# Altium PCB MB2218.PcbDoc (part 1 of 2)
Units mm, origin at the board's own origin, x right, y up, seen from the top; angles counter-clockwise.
Board outline 43 x 47 mm, 4 copper layers (Top Layer, Signal Layer 1, Signal Layer 2, Bottom Layer), stack 1.539 mm thick; 90 components, 71 nets, 361 pads, 605 vias.
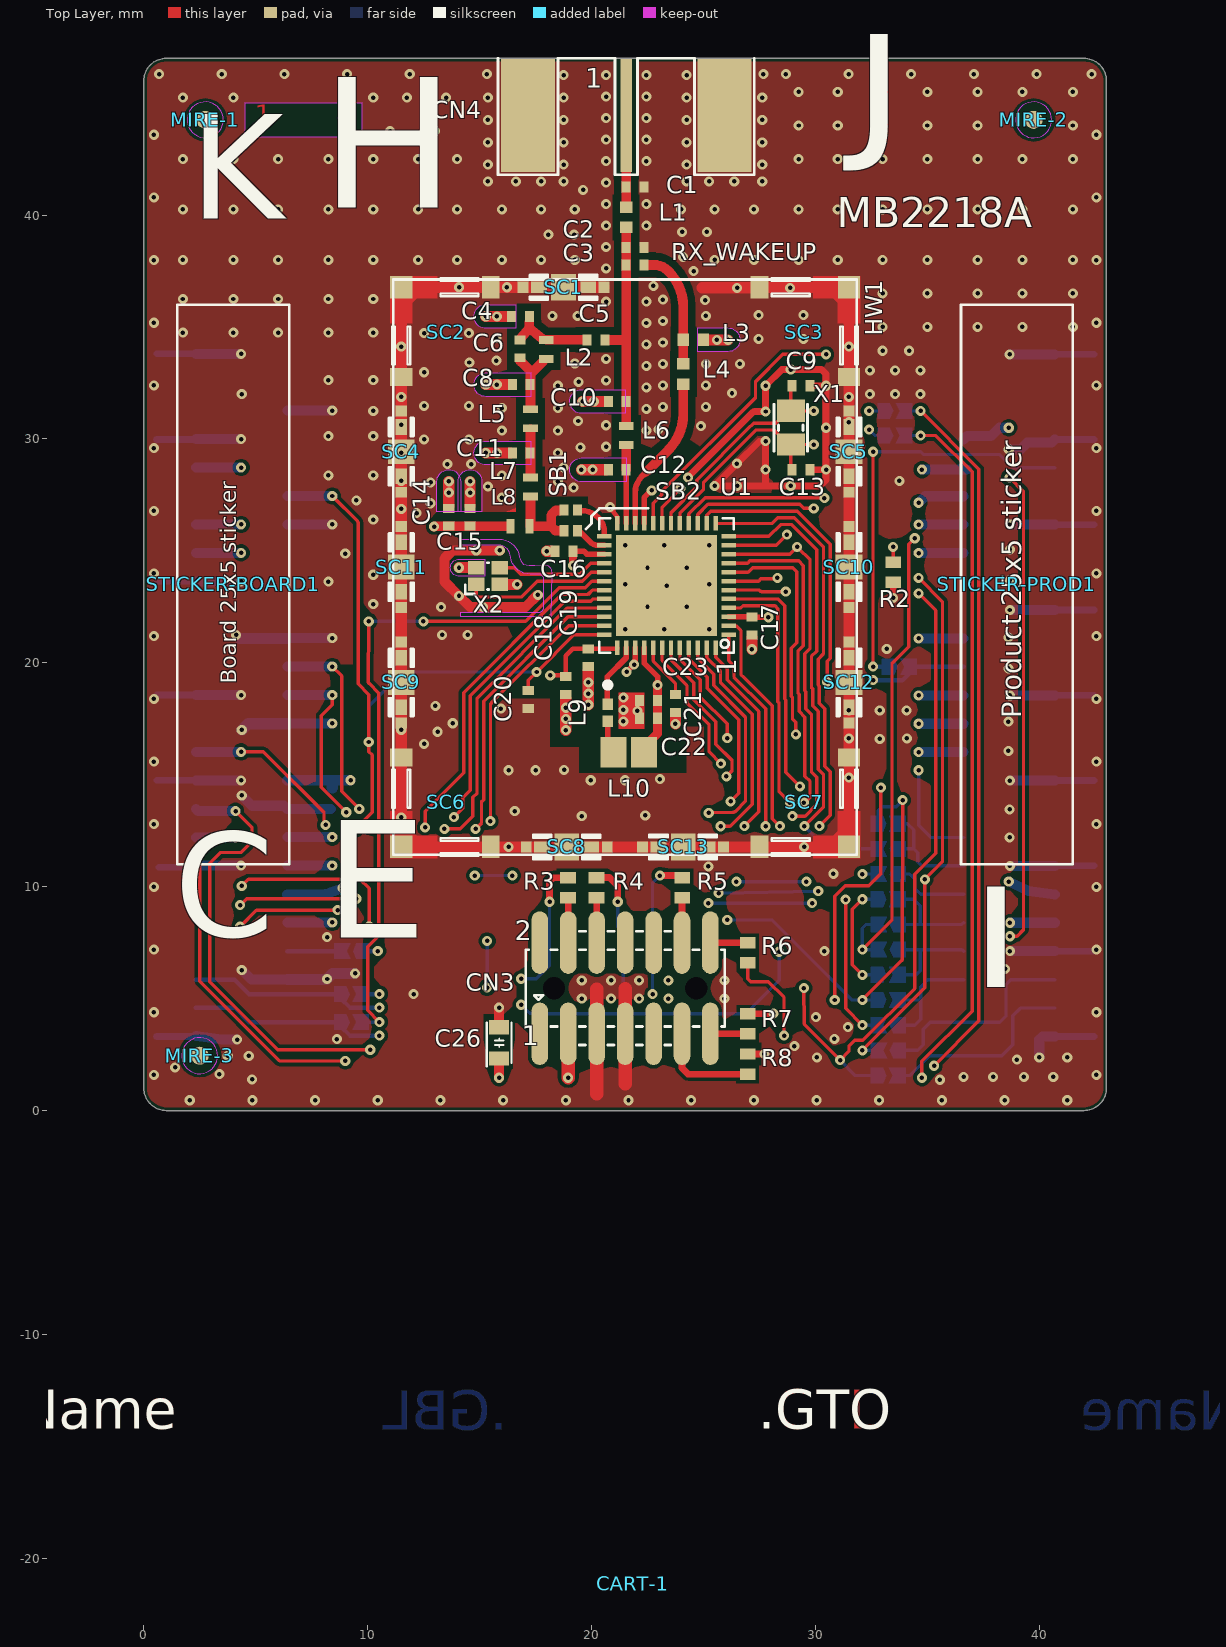
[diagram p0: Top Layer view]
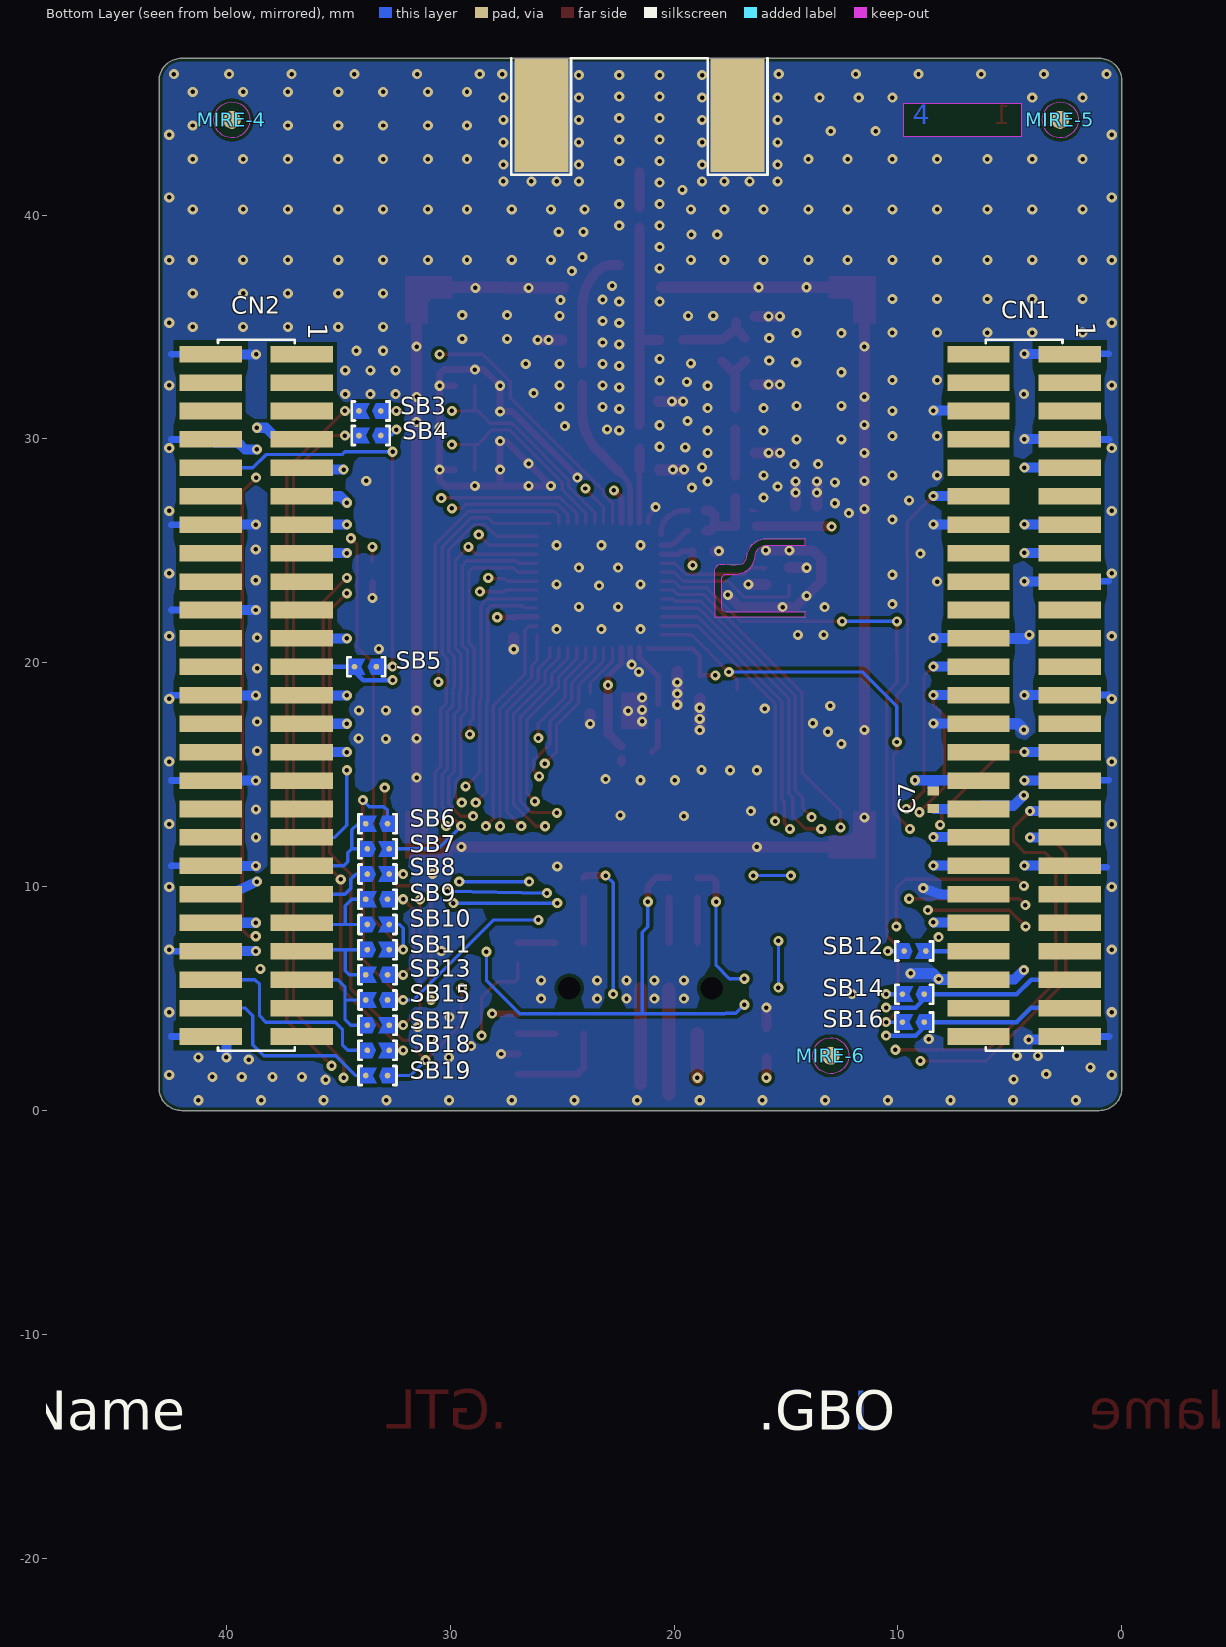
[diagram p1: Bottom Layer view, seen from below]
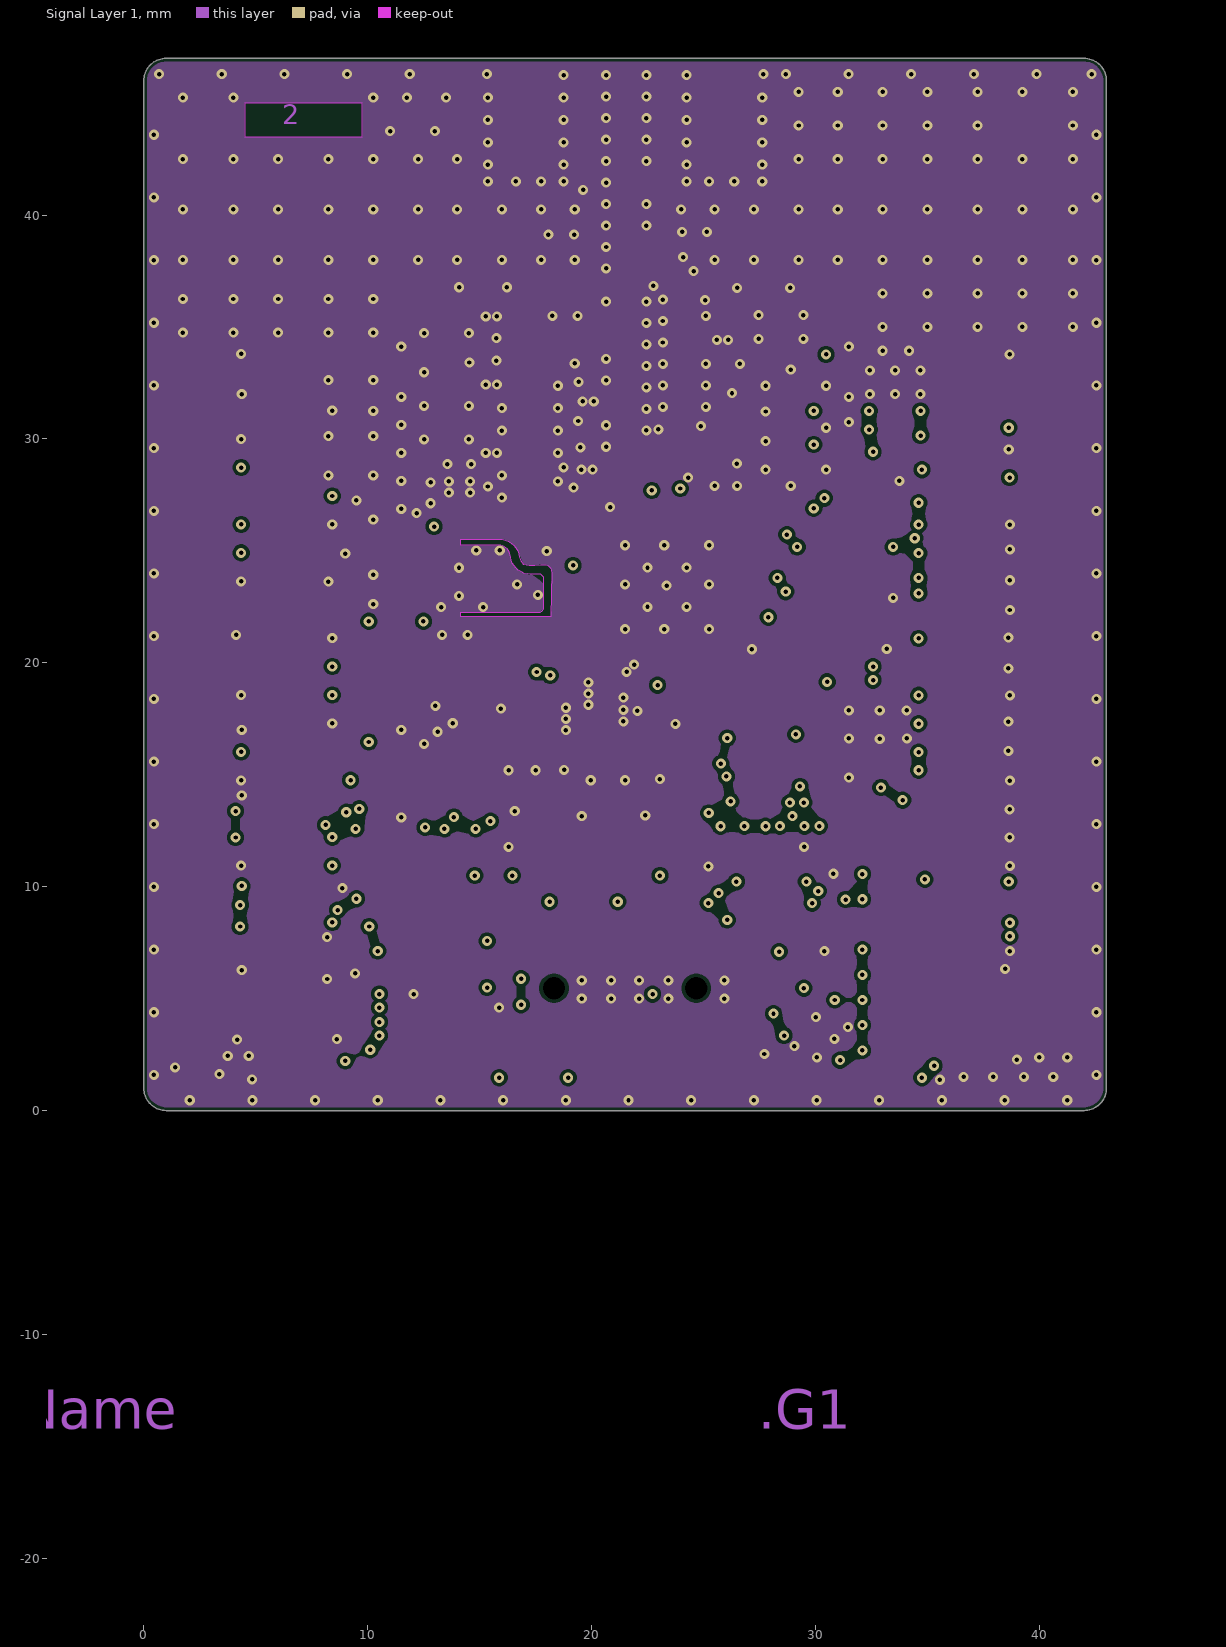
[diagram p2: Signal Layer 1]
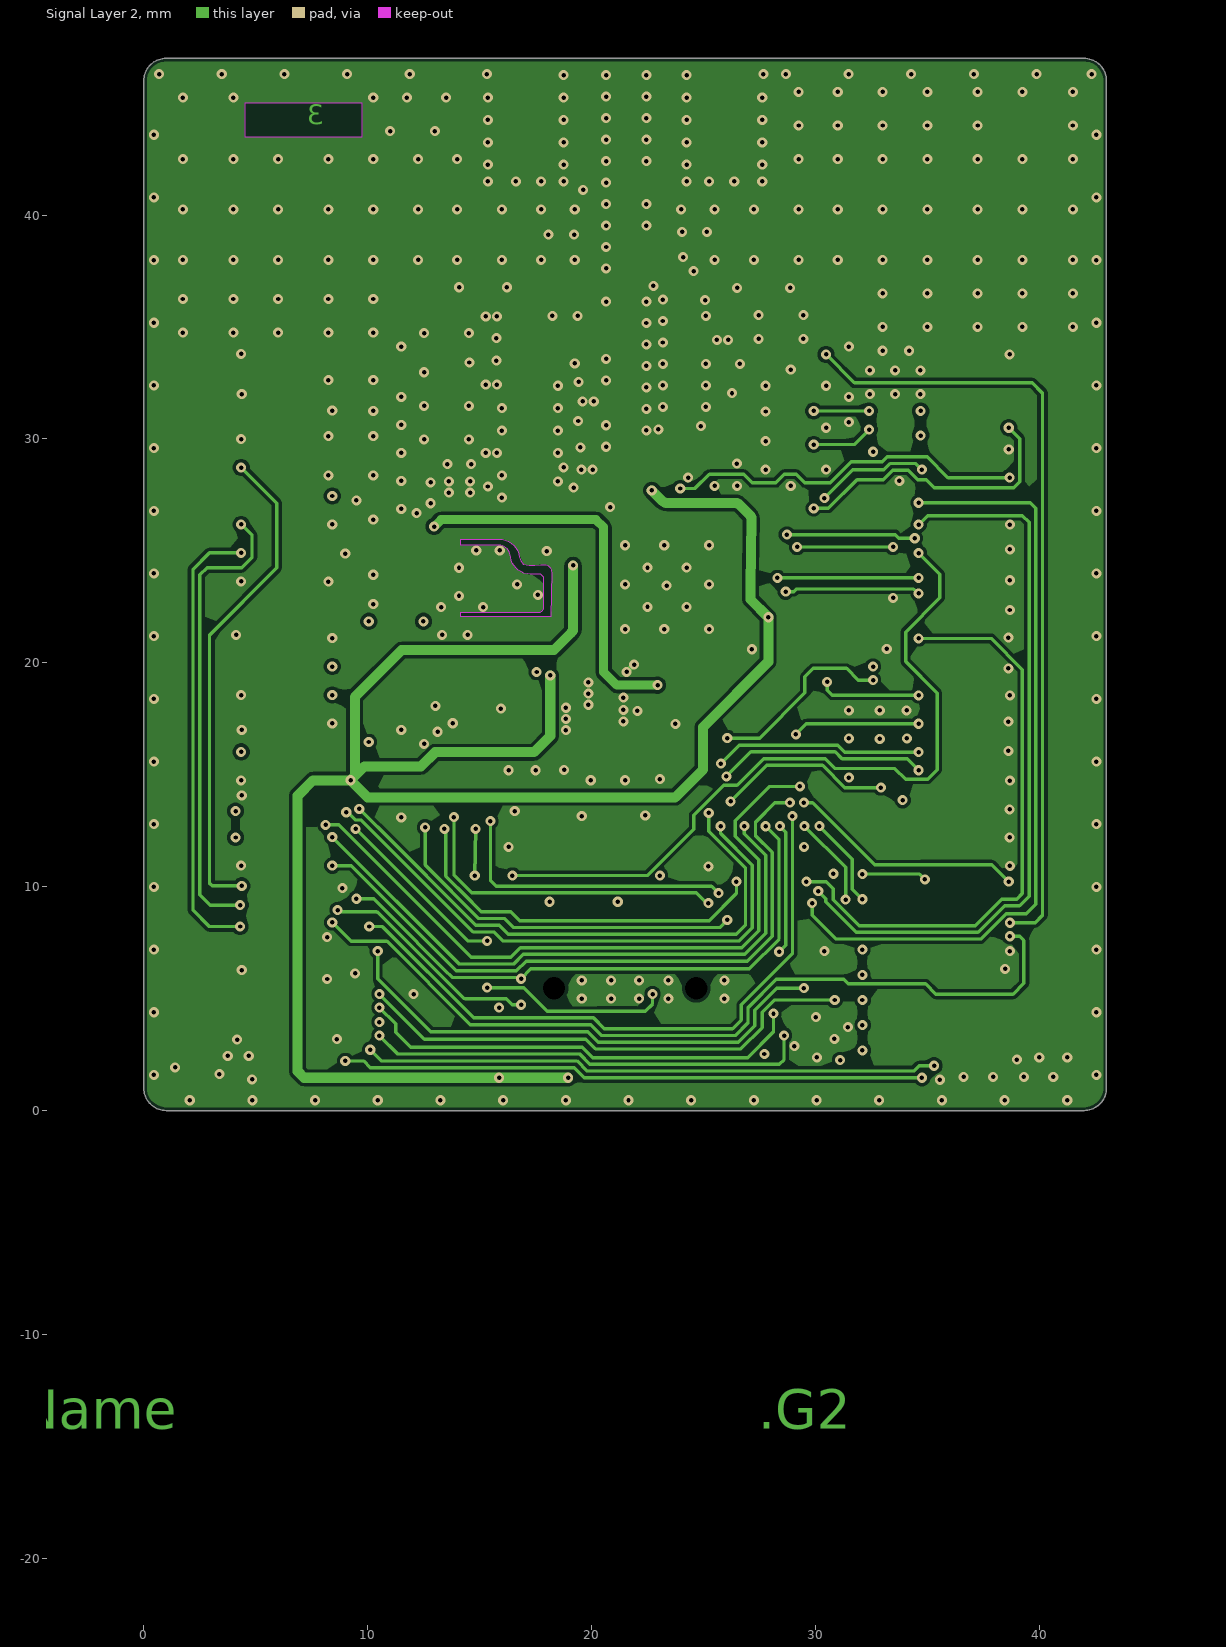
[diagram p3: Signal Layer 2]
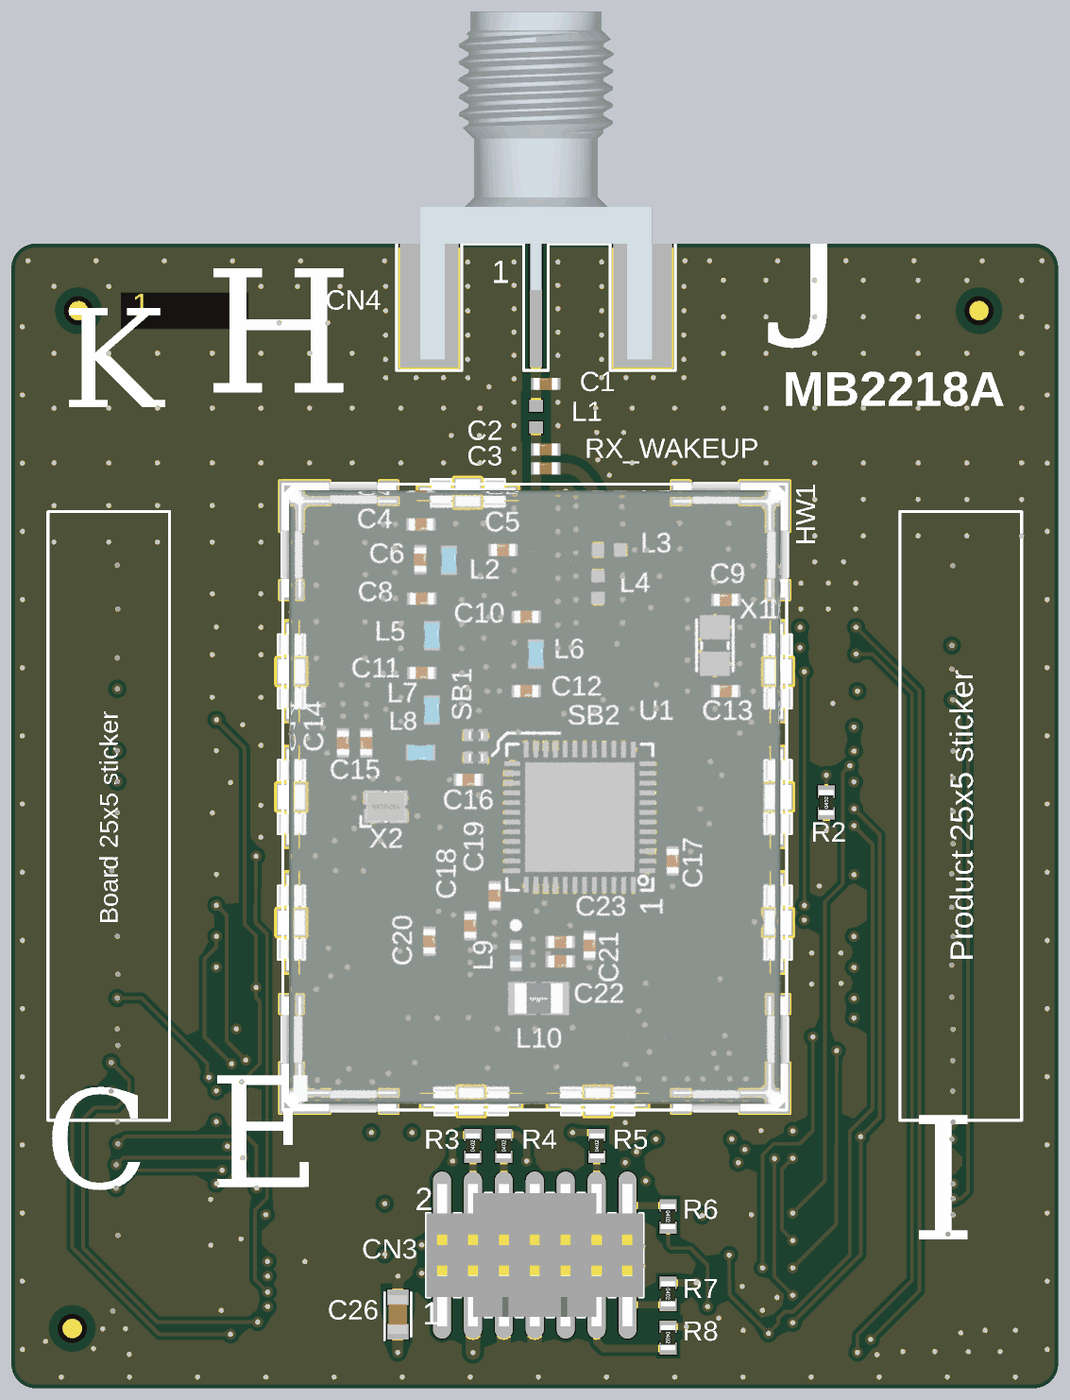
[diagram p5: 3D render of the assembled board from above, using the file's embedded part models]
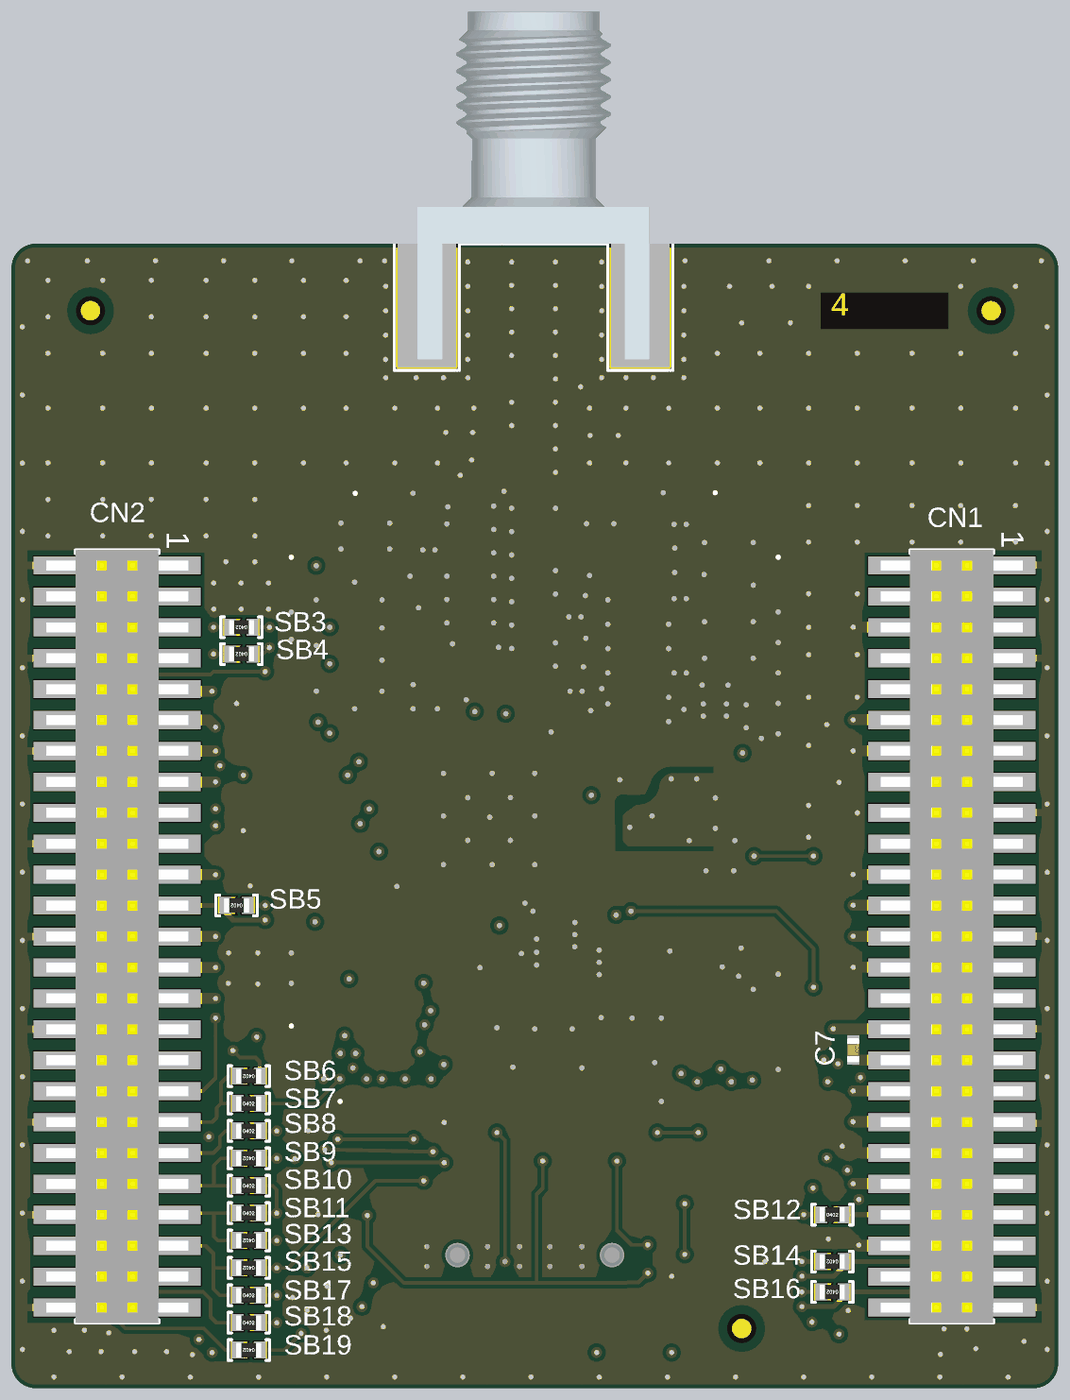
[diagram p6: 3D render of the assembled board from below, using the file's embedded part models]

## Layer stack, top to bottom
Top Solder: solder mask 0.0102, Solder Resist, Dk 3.5
Top Layer: signal copper 0.0406
Dielectric 1: core 0.254, FR4 VT-47, Dk 4
Signal Layer 1: signal copper 0.0178
Dielectric 2: core 0.9144, FR4 VT-47, Dk 4.3
Signal Layer 2: signal copper 0.0178
Dielectric 3: core 0.254, FR4 VT-47, Dk 4
Bottom Layer: signal copper 0.0406
Bottom Solder: solder mask 0.0102, Solder Resist, Dk 3.5

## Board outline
0,1 ccw(c1,1) 1,0 42,0 ccw(c42,1) 43,1 43,46 ccw(c42,46) 42,47 1,47 ccw(c1,46) 0,46

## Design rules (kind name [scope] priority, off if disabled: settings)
BoardOutlineClearance [All] p1: gap=0.14 ignorepadtopadclearanceinfootprint=FALSE
Clearance Clearance_Keepout [All vs IsKeepOut] p1: gap=0.15 ignorepadtopadclearanceinfootprint=TRUE except(0: Poly-Region)
Clearance Clearance_RF-50R [InNetClass('NC_RF-50R')] p2: gap=0.335 ignorepadtopadclearanceinfootprint=FALSE except(0.15: Arc-Arc Arc-Track Arc-SMDPad Arc-Via Track-Track Track-SMDPad Track-Via SMDPad-Via Via-Via Via-Fill Via-Region Via-Text Via-Hole; 0.2: SMDPad-SMDPad)
Clearance Clearance_Default_Same-net_GND [InNet('GND')] p3: gap=0.15 ignorepadtopadclearanceinfootprint=TRUE except(0: Arc-SMDPad Arc-Via Track-SMDPad Track-Via Track-Hole SMDPad-Via SMDPad-Hole THPad-Via Via-Via Via-Region Via-Hole; 0.12: SMDPad-SMDPad)
Clearance Clearance_Default_Same-net [All] p4: gap=0.15 ignorepadtopadclearanceinfootprint=TRUE except(0.1: Via-Via; 0.12: Arc-SMDPad Track-SMDPad SMDPad-SMDPad)
Clearance Clearance_Default [All] p5: gap=0.15 ignorepadtopadclearanceinfootprint=FALSE except(0.1: Arc-Via Track-Via)
ComponentClearance [All] p1: gap=0.165 collisioncheckmode=3 verticalgap=0.165 showdistances=FALSE
HoleSize [All] p1: absolutevalues=TRUE maxlimit=10 minlimit=0.025 maxpercent=80.000 minpercent=20.000
HoleToHoleClearance [All] p1: gap=0.2 allowstackedmicrovias=TRUE
MinimumSolderMaskSliver [All] p1: minsoldermaskwidth=0.1
PlaneConnect [All] p1: planeconnectstyle=Relief reliefexpansion=0.508 reliefentries=4 reliefconductorwidth=0.21 reliefairgap=0.21
PolygonConnect PolygonConnect_clip [TouchesRoom('RoomDefinition')or TouchesRoom('RoomDefinition_2') or   TouchesRoom('RoomDefinition_1') OR TouchesRoom('RoomDefinition_3') or  TouchesRoom('RoomDefinition_4')  or TouchesRoom('RoomDefinition_5')] p1: connectstyle=Direct reliefconductorwidth=0.254 reliefentries=4 polygonreliefangle="90 Angle" airgapwidth=0.254
PolygonConnect PolygonConnect_Default [All] p2: thpad.connectstyle=Relief thpad.reliefconductorwidth=0.3 thpad.reliefentries=4 thpad.polygonreliefangle="90 Angle" thpad.airgapwidth=0.25 smdpad.connectstyle=NoConnect smdpad.reliefconductorwidth=0.254 smdpad.reliefentries=4 smdpad.polygonreliefangle="90 Angle" smdpad.airgapwidth=0.254 via.connectstyle=Direct via.reliefconductorwidth=0.254 via.reliefentries=4 via.polygonreliefangle="90 Angle" via.airgapwidth=0.254
RoomDefinition RoomDefinition_5 [False vs False] p1: confinementstyle=ConfineIn formatcopy=TRUE lockcomponents=FALSE outline 20.2,27.657 21.45,27.657 21.45,25.9 20.2,25.9
RoomDefinition RoomDefinition_4 [False vs False] p2: confinementstyle=ConfineIn formatcopy=TRUE lockcomponents=FALSE outline 16.668,18.313 18.139,18.313 18.139,17.066 16.668,17.066
RoomDefinition RoomDefinition_3 [False vs False] p3: confinementstyle=ConfineIn formatcopy=TRUE lockcomponents=FALSE outline 22.14,41.754 23.059,41.754 23.059,38.308 22.14,38.308
RoomDefinition RoomDefinition_1 [False vs False] p4: confinementstyle=ConfineIn formatcopy=TRUE lockcomponents=FALSE outline 30.617,26.64 32.517,26.64 32.517,16.661 30.617,16.661
RoomDefinition [False vs False] p5: confinementstyle=ConfineIn formatcopy=TRUE lockcomponents=FALSE outline 10.617,26.639 12.517,26.639 12.517,16.661 10.617,16.661
RoomDefinition RoomDefinition_2 [False] p6: confinementstyle=ConfineIn formatcopy=TRUE lockcomponents=FALSE outline 15.917,11.028 15.917,12.613 26.825,12.613 26.825,11.028
RoutingVias RoutingVias_Default [All] p1: holewidth=0.3 width=0.6 viastyle="Through Hole" minholewidth=0.3 minwidth=0.6 maxholewidth=0.3 maxwidth=0.6 useviatemplates=TRUE viatemplateguid#1={99C878AE-A8D1-4413-99BF-86AA8753CADB} viatemplatename#1=v45h20m0mx0
SilkToSilkClearance [All] p1 off: silktosilkclearance=0.2
SilkToSolderMaskClearance [IsPad] p1 off: minsilkscreentomaskgap=0.2 clearancetoexposedcopper=TRUE
SolderMaskExpansion [All] p1: expansion=0.102 istentingtop=FALSE
ViasUnderSMD [InPadClass('PC__VIAS-IN-PAD')] p1: allowed=TRUE
Width Width_RF-50R [InNetClass('NC_RF-50R')] p1: maxlimit=0.45 minlimit=0.25 preferedwidth=0.254 toplayer_prefwidth=0.44 impedanceprofiledriven=TRUE impedanceprofileid={AD1550EC-3D0E-4E34-9E21-FD44D1EEEC04} impedanceprofilevalue=50.000000 minimp=50.000000 maximp=50.000000 favimp=50.000000
Width Width_Default [All] p2: maxlimit=10 minlimit=0.15 preferedwidth=0.2
23 further rules are at their usual default settings.

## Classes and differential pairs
pad class PC__VIAS-IN-PAD: C22-1 C22-2 C23-1 C23-2 U1-49
net class NC_RF-50R: NetC1_2 NetC2_2 NetC3_1 NetC4_2 NetC6_1 NetC11_2 NetC12_2 NetL4_1 NetL7_1

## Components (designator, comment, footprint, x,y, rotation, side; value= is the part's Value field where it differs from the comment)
C1 "Capacitor" GRM155--GJM155-0_05-MFG 21.95,41.25 r180 top value=TBD
C2 "Capacitor" GRM155--GJM155-0_05-MFG 21.95,38.55 r180 top value=TBD
C3 "Capacitor" GRM155--GJM155-0_05-MFG 21.95,37.775 r180 top value=TBD
C4 "Capacitor" GRM155--GJM155-0_05-MFG 16.825,35.475 r0 top value=TBD
C5 "Capacitor" GRM155--GJM155-0_05-MFG 20.2,34.425 r180 top value=TBD
C6 "Capacitor" GRM155--GJM155-0_05-MFG 16.8,34.025 r90 top value=TBD
C7 "Capacitor" GRM155--GJM155-0_05-MFG 8.42,13.882 r90 bottom value=TBD
C8 "Capacitor" GRM155--GJM155-0_05-MFG 16.86,32.425 r0 top value=TBD
C9 "Capacitor" GRM155--GJM155-0_05-MFG 29.35,32.375 r180 top value=6.8pF
C10 "Capacitor" GRM155--GJM155-0_05-MFG 21.15,31.675 r0 top value=TBD
C11 "Capacitor" GRM155--GJM155-0_05-MFG 16.86,29.375 r0 top value=TBD
C12 "Capacitor" GRM155--GJM155-0_05-MFG 21.15,28.625 r0 top value=TBD
C13 "Capacitor" GRM155--GJM155-0_05-MFG 29.35,28.625 r180 top value=6.8pF
C14 "Capacitor" GRM155--GJM155-0_05-MFG 13.625,26.5 r90 top value=100pF
C15 "Capacitor" GRM155--GJM155-0_05-MFG 14.575,26.5 r270 top value=100nF
C16 "Capacitor" GRM155--GJM155-0_05-MFG 18.775,24.985 r0 top value=100nF
C17 "Capacitor" GRM155--GJM155-0_05-MFG 27.163,21.65 r90 top value=100nF
C18 "Capacitor" GRM155--GJM155-0_05-MFG 18.852,18.99 r90 top value=4.7uF
C19 "Capacitor" GRM155--GJM155-0_05-MFG 19.857,20.225 r90 top value=TBD
C20 "Capacitor" GRM155--GJM155-0_05-MFG 17.172,18.352 r90 top value=100nF
C21 "Capacitor" GRM155--GJM155-0_05-MFG 23.75,18.175 r90 top value=220nF
C22 "Capacitor" GRM155--GJM155-0_05-MFG 22.55,17.525 r0 top value=4.7uF
C23 "Capacitor" GRM155--GJM155-0_05-MFG 22.55,18.321 r180 top value=100nF
C26 "Capacitor" C0603 15.875,3.025 r270 top value=1uF
CART-1 "Comment" Sheetbox_4L2S -23.25,-26.5 r0 top
CN1 "FTSH-125-02-L-DV" CON_SAMTEC_FTSH-125-02-L-DV_INV 4.366,18.548 r270 bottom locked value="Header 25x2"
CN2 "FTSH-125-02-L-DV" CON_SAMTEC_FTSH-125-02-L-DV_INV 38.656,18.548 r270 bottom locked value="Header 25x2"
CN3 "Header 7x2" CON_SAMTEC_FTSH-107-01-L-DV-K-A 21.5,5.465 r0 top locked
CN4 "mmcx" CON_SMA-RF_CINCH_142-0701-851 21.55,47 r0 top
HW1 "S02-20150300" SHIELD_HARWIN_S02-25200300_20X25_H3 21.5,24.275 r0 top locked value=S02-25200300R
L1 "Inductor" L0402 21.55,39.9 r90 top value=0R
L2 "Inductor" LQW15AN_00-W0_6-0_1-MFG 17.975,34 r90 top value=TBD
L3 "Inductor" L0402 24.55,34.425 r0 top value=TBD
L4 "Inductor" L0402 24.1,32.9 r90 top value=TBD
L5 "Inductor" LQW15AN_00-W0_6-0_1-MFG 17.275,30.9 r90 top value=TBD
L6 "Inductor" LQW15AN_00-W0_6-0_1-MFG 21.55,30.15 r90 top value=TBD
L7 "Inductor" LQW15AN_00-W0_6-0_1-MFG 17.275,27.85 r90 top value=TBD
L8 "Inductor" LQW15AN_00-W0_6-0_1-MFG 16.81,26.1 r0 top value=TBD
L9 "Inductor" LQG15HH_02-IPC_C 20.725,17.773 r270 top value=100nH
L10 "Inductor" LQM21FN_70-IPC_C 21.663,16.008 r180 top value=10µH
MIRE-1 "Comment" MIRE_PLACE_SMD_0P8MM 2.75,44.25 r0 top
MIRE-2 "Comment" MIRE_PLACE_SMD_0P8MM 39.75,44.25 r0 top
MIRE-3 "Comment" MIRE_PLACE_SMD_0P8MM 2.5,2.45 r0 top
MIRE-4 "Comment" MIRE_PLACE_SMD_0P8MM 39.75,44.25 r180 bottom
MIRE-5 "Comment" MIRE_PLACE_SMD_0P8MM 2.75,44.25 r180 bottom
MIRE-6 "Comment" MIRE_PLACE_SMD_0P8MM 13,2.45 r180 bottom
R2 "Resistor" R0402 33.475,24.05 r90 top value=100K
R3 "Resistor" R0402 18.95,9.95 r90 top value=47R
R4 "Resistor" R0402 20.225,9.95 r90 top value=47R
R5 "Resistor" R0402 24.05,9.95 r90 top value=47R
R6 "Resistor" R0402 26.975,7.05 r270 top value=47R
R7 "Resistor" R0402 26.975,3.875 r270 top value=47R
R8 "Resistor" R0402 26.975,2.075 r270 top value=47R
SB1 "SB_ON" SOLDER-BRIDGE_R0201_0R 19.075,26.821 r180 top value=0R
SB2 "SB_ON" SOLDER-BRIDGE_R0201_0R 19.075,25.9 r180 top value=0R
SB3 "SB_ON" SOLDER-BRIDGE_R0402-0R 33.55,31.25 r0 bottom
SB4 "SB_ON" SOLDER-BRIDGE_R0402-0R 33.55,30.15 r0 bottom
SB5 "SB_ON" SOLDER-BRIDGE_R0402-0R 33.75,19.825 r0 bottom
SB6 "SB_ON" SOLDER-BRIDGE_R0402-0R 33.25,12.812 r0 bottom
SB7 "SB_ON" SOLDER-BRIDGE_R0402-0R 33.25,11.688 r180 bottom
SB8 "SB_ON" SOLDER-BRIDGE_R0402-0R 33.25,10.563 r180 bottom
SB9 "SB_ON" SOLDER-BRIDGE_R0402-0R 33.25,9.437 r0 bottom
SB10 "SB_ON" SOLDER-BRIDGE_R0402-0R 33.25,8.313 r180 bottom
SB11 "SB_ON" SOLDER-BRIDGE_R0402-0R 33.25,7.187 r180 bottom
SB12 "SB_ON" SOLDER-BRIDGE_R0402-0R 9.275,7.125 r180 bottom
SB13 "SB_ON" SOLDER-BRIDGE_R0402-0R 33.25,6.062 r0 bottom
SB14 "SB_ON" SOLDER-BRIDGE_R0402-0R 9.275,5.2 r0 bottom
SB15 "SB_ON" SOLDER-BRIDGE_R0402-0R 33.25,4.938 r0 bottom
SB16 "SB_ON" SOLDER-BRIDGE_R0402-0R 9.275,3.95 r0 bottom
SB17 "SB_ON" SOLDER-BRIDGE_R0402-0R 33.25,3.812 r180 bottom
SB18 "SB_ON" SOLDER-BRIDGE_R0402-0R 33.25,2.688 r180 bottom
SB19 "SB_ON" SOLDER-BRIDGE_R0402-0R 33.25,1.562 r0 bottom
SC1 "Shield-clip_S0951-46R" CLIP_HARWIN_S0951-46R 18.75,36.775 r180 top value=S0951-46R
SC2 "Shield-clip_S0951-46R" CLIP_HARWIN_S0981-46R 11.5,36.775 r180 top value=S0981-46R
SC3 "Shield-clip_S0951-46R" CLIP_HARWIN_S0981-46R 31.5,36.775 r90 top value=S0981-46R
SC4 "Shield-clip_S0951-46R" CLIP_HARWIN_S0951-46R 11.5,29.433 r90 top value=S0951-46R
SC5 "Shield-clip_S0951-46R" CLIP_HARWIN_S0951-46R 31.5,29.433 r90 top value=S0951-46R
SC6 "Shield-clip_S0951-46R" CLIP_HARWIN_S0981-46R 11.5,11.775 r270 top value=S0981-46R
SC7 "Shield-clip_S0951-46R" CLIP_HARWIN_S0981-46R 31.5,11.775 r0 top value=S0981-46R
SC8 "Shield-clip_S0951-46R" CLIP_HARWIN_S0951-46R 18.89,11.775 r180 top value=S0951-46R
SC9 "Shield-clip_S0951-46R" CLIP_HARWIN_S0951-46R 11.5,19.12 r270 top value=S0951-46R
SC10 "Shield-clip_S0951-46R" CLIP_HARWIN_S0951-46R 31.5,24.278 r90 top value=S0951-46R
SC11 "Shield-clip_S0951-46R" CLIP_HARWIN_S0951-46R 11.5,24.278 r270 top value=S0951-46R
SC12 "Shield-clip_S0951-46R" CLIP_HARWIN_S0951-46R 31.5,19.12 r90 top value=S0951-46R
SC13 "Shield-clip_S0951-46R" CLIP_HARWIN_S0951-46R 24.09,11.775 r180 top value=S0951-46R
STICKER-BOARD1 "Comment" STICKER_BOARD_25X5 4,23.5 r90 top
STICKER-PROD1 "Comment" STICKER_PRODUCT_25X5 39,23.5 r90 top
U1 "STM32WL33" ICC_QFN48-EPAD-4P5X4P5_6X6_P040 23.35,23.45 r180 top
X1 "XTAL_2_PINS" CRY_NX2012SA_2P 28.9,30.5 r90 top value=32.768kHz
X2 "XTAL_4_PINS" CRY_NX1612SA_4P 15.38,23.875 r0 top locked value=48MHz

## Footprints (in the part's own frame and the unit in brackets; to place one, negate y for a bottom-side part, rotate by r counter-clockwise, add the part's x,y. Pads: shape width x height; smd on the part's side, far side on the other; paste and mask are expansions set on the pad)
C0603 [mm]
  rect 0.64x0.89 smd mask+0.05: 1(-0.7,0) 2(0.7,0)
  silkscreen extent -0.9,-0.55 1.05,0.55, body extent -0.9,-0.5 0.9,0.5, height 1.4
CLIP_HARWIN_S0951-46R [mm] "MCD-01587_CLIP-X1"
  rect 0.48x0.5 smd mask+0.1: 1(-1.81,0) 1(1.81,0)
  rect 0.7x0.5 smd mask+0.1: 1(-1.1,0) 1(1.1,0)
  rect 1.1x1.2 smd mask+0.1: 1(0,0)
  silkscreen extent -1.5,-0.55 1.5,0.55, body extent -2.05,-0.65 2.05,0.65, height 1.28
CLIP_HARWIN_S0981-46R [mm] "MCD-02164"
  rect 0.8x1 smd mask+0.05: 1(-4,0)
  rect 1x0.8 smd mask+0.05: 1(0,4)
  rect 1x1 smd mask+0.05: 1(0,0)
  Top Layer region: -1.6,-0.5 0.5,-0.5 0.5,1.6 -0.5,1.6 -0.5,0.7 -0.7,0.5 -1.6,0.5
  silkscreen extent -3.45,-0.4 0.4,3.45, body extent -4.3,-0.46 0.46,4.3, height 1.4
CON_SAMTEC_FTSH-107-01-L-DV-K-A [mm] "MCD-01959"
  oval 0.74x2.79 smd mask+0.05: 1(-3.81,-2.035) 2(-3.81,2.035) 3(-2.54,-2.035) 4(-2.54,2.035) 5(-1.27,-2.035) 6(-1.27,2.035) 7(0,-2.035) 8(0,2.035) 9(1.27,-2.035) 10(1.27,2.035) 11(2.54,-2.035) 12(2.54,2.035) 13(3.81,-2.035) 14(3.81,2.035)
  round 0 hole 1 unplated paste-2539.97 mask+0.05: NPTH1(-3.175,0) NPTH2(3.175,0)
  silkscreen extent -4.44,-2.54 4.44,2.54, body extent -4.44,-2.92 4.45,2.92, height 6.12
CON_SAMTEC_FTSH-125-02-L-DV_INV [mm]
  rect 0.74x2.79 smd mask+0.05: 1(-15.24,2.035) 2(-15.24,-2.035) 3(-13.97,2.035) 4(-13.97,-2.035) 5(-12.7,2.035) 6(-12.7,-2.035) 7(-11.43,2.035) 8(-11.43,-2.035) 9(-10.16,2.035) 10(-10.16,-2.035) 11(-8.89,2.035) 12(-8.89,-2.035) 13(-7.62,2.035) 14(-7.62,-2.035) 15(-6.35,2.035) 16(-6.35,-2.035) 17(-5.08,2.035) 18(-5.08,-2.035) 19(-3.81,2.035) 20(-3.81,-2.035) 21(-2.54,2.035) 22(-2.54,-2.035) 23(-1.27,2.035) 24(-1.27,-2.035) 25(0,2.035) 26(0,-2.035) 27(1.27,2.035) 28(1.27,-2.035) 29(2.54,2.035) 30(2.54,-2.035) 31(3.81,2.035) 32(3.81,-2.035) 33(5.08,2.035) 34(5.08,-2.035) 35(6.35,2.035) 36(6.35,-2.035) 37(7.62,2.035) 38(7.62,-2.035) 39(8.89,2.035) 40(8.89,-2.035) 41(10.16,2.035) 42(10.16,-2.035) 43(11.43,2.035) 44(11.43,-2.035) 45(12.7,2.035) 46(12.7,-2.035) 47(13.97,2.035) 48(13.97,-2.035) 49(15.24,2.035) 50(15.24,-2.035)
  silkscreen extent -15.88,-1.71 15.88,1.71, body extent -15.87,-2.92 15.88,2.92, height 4.82
CON_SMA-RF_CINCH_142-0701-851 [mil] "MCD-02072"
  rect 20.08x200 smd mask+1.97: 1(0,-100)
  rect 95x200 smd mask+1.97: 2(172.48,-100) 3(-172.48,-100)
  rect 95x200 smd far side mask+1.97: 4(-172.48,-100) 5(172.48,-100)
  silkscreen extent -225,-205 225,0, body extent -189,-187 189,376, height 161
CRY_NX1612SA_4P [mm] "MCD-02262"
  rect 0.75x0.6 smd mask+0.038: 1(-0.525,-0.375) 2(0.525,-0.375) 3(0.525,0.375) 4(-0.525,0.375)
  silkscreen extent -1.02,-0.8 0.03,0.6, body extent -0.8,-0.6 0.8,0.6, height 0.31
CRY_NX2012SA_2P [mm]
  rect 1x1.25 smd mask+0.05: 1(-0.75,0) 2(0.75,0)
  silkscreen extent -1.05,-0.75 1.05,0.75, body extent -1.05,-0.63 1.05,0.63, height 0.6
GRM155--GJM155-0_05-MFG [mm]
  rect 0.4x0.5 smd paste+0 mask+0: 1(-0.4,0) 2(0.4,0)
  body extent -0.7,-0.38 0.7,0.38, height 0.25
ICC_QFN48-EPAD-4P5X4P5_6X6_P040 [mm] "MCD-03488"
  rect 0.65x0.2 smd mask+0.05: 1(-2.775,2.2) 2(-2.775,1.8) 3(-2.775,1.4) 4(-2.775,1) 5(-2.775,0.6) 6(-2.775,0.2) 7(-2.775,-0.2) 8(-2.775,-0.6) 9(-2.775,-1) 10(-2.775,-1.4) 11(-2.775,-1.8) 12(-2.775,-2.2) 25(2.775,-2.2) 26(2.775,-1.8) 27(2.775,-1.4) 28(2.775,-1) 29(2.775,-0.6) 30(2.775,-0.2) 31(2.775,0.2) 32(2.775,0.6) 33(2.775,1) 34(2.775,1.4) 35(2.775,1.8) 36(2.775,2.2)
  rect 0.2x0.65 smd mask+0.05: 13(-2.2,-2.775) 14(-1.8,-2.775) 15(-1.4,-2.775) 16(-1,-2.775) 17(-0.6,-2.775) 18(-0.2,-2.775) 19(0.2,-2.775) 20(0.6,-2.775) 21(1,-2.775) 22(1.4,-2.775) 23(1.8,-2.775) 24(2.2,-2.775) 37(2.2,2.775) 38(1.8,2.775) 39(1.4,2.775) 40(1,2.775) 41(0.6,2.775) 42(0.2,2.775) 43(-0.2,2.775) 44(-0.6,2.775) 45(-1,2.775) 46(-1.4,2.775) 47(-1.8,2.775) 48(-2.2,2.775)
  rect 4.5x4.5 smd mask+0.05: 49(0,0)
  silkscreen extent -3,-3 3,3, body extent -3,-3 3,3, height 0.91
L0402 [mm]
  rect 0.51x0.56 smd mask+0.05: 1(-0.45,0) 2(0.45,0)
  body extent -0.5,-0.3 0.5,0.3, height 0.51
LQG15HH_02-IPC_C [mm]
  rect 0.515x0.472 smd paste+0 mask+0: 1(-0.379,0) 2(0.379,0)
  silkscreen extent -1.36,-0.12 -1.11,0.13, body extent -0.74,-0.38 0.74,0.38, height 0.25
LQM21FN_70-IPC_C [mm]
  rect 1.154x1.356 smd paste+0 mask+0: 1(-0.676,0) 2(0.676,0)
  body extent -1.35,-0.82 1.35,0.82, height 0.25
LQW15AN_00-W0_6-0_1-MFG [mm]
  rect 0.35x0.65 smd paste+0 mask+0: 1(-0.425,0) 2(0.425,0)
  body extent -0.7,-0.45 0.7,0.45, height 0.25
MIRE_PLACE_SMD_0P8MM [mm]
  round 0.8 smd paste-10 mask+0.2: 1(0,0)
  Top Layer keep-out circle w0.01: c0,0 r0.804
R0402 [mm]
  rect 0.51x0.7 smd mask+0.05: 1(-0.45,0) 2(0.45,0)
  body extent -0.52,-0.3 0.52,0.3, height 0.4
Sheetbox_4L2S [mil] "Sheetbox 4 layers / 2 silkscreens"
  round 20 on Mech16: 1(813.78,210.69) 1(2736.9,210.69)
SHIELD_HARWIN_S02-25200300_20X25_H3 [mm] "MCD-03503"
  silkscreen extent -10.35,-12.85 10.35,12.85, body extent -10.1,-12.6 10.1,12.6, height 3.2
SOLDER-BRIDGE_R0201_0R [mm] "MCD-03219"
  rect 0.4x0.5 smd mask+0.05: 1(-0.3,0) 2(0.3,0)
  body extent -0.32,-0.17 0.32,0.17, height 0.26
SOLDER-BRIDGE_R0402-0R [mil] "MCD-01619"
  round 10 smd paste-393.7: 1(-17.72,0) 2(20.67,0)
  Top Layer region: 1.48,13.78 8.37,0 1.48,-13.78 30.51,-13.78 30.51,13.78
  Top Layer region: -30.51,-13.78 -30.51,13.78 -8.86,13.78 -2.95,0 -8.86,-13.78
  silkscreen extent -33,-17 33,17, body extent -20,-12 20,12, height 14
STICKER_BOARD_25X5 [mm] "Sticker to mention board reference + serial number"
  silkscreen extent -12.5,-2.5 12.5,2.5
STICKER_PRODUCT_25X5 [mm] "Sticker to mention board CPN code"
  silkscreen extent -12.5,-2.5 12.5,2.5

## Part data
C1 C2: library part MCD-01600, "Capacitor, MLCC, 1pF, 50V, NPO, +/-0.1pF, 0402, T=0.5mm", Manufacturer=TBD, Package=0402
C3: library part MCD-03446, "Capacitor, MLCC, 100pF, 50V, COG, +/-1%, 0402, T=0.5mm", Manufacturer=MURATA, Package=0402
C4: library part MCD-03448, "Capacitor, MLCC, 2.7pF, 50V, C0G, +/-0.05pF, C0G, 0402, T=0.5mm", Manufacturer=MURATA, Package=0402
C5 C7: library part MCD-03446, "Capacitor, MLCC, 100pF, 50V, COG, 1%, 0402, T=0.5mm", Manufacturer=MURATA, Package=0402
C6: library part MCD-02065, "Capacitor, Monolithic CC, 1.2pF, 50V, +/-0.05pf, 0402, T=0.5mm", Manufacturer=MURATA, Package=0402
C8: library part MCD-01374, "Capacitor, MLCC, 5.6pF, 50V, NPO, +/-0.1pF, 0402, T=0.5mm", Package=0402
C9 C13: library part MCD-03452, "Capacitor, MLCC, 6.8pF, ±0.05pF, C0G, 50V, 0402, T=0.5mm", Manufacturer=MURATA, Manufacturer_Part_Number=GJM1555C1H6R8WB01, Package=0402
C10: library part MCD-02994, "Capacitor, MLCC, 1.5pF, 50V, C0G, +/-0.25pF, 0402, T=0.5mm", Manufacturer=MURATA, Package=0402
C11: library part MCD-03555, "Capacitor, MLCC, 5.3pF, 50V, C0G, +/-0.1pF, 0402, T=0.5mm", Manufacturer=MURATA, Package=0402
C12: library part MCD-02215, "Capacitor, MLCC, 0.5pF, 50V, C0G, +/-0.1pF, 0402, T=0.5mm", Manufacturer=MURATA, Package=0402
C14: library part MCD-03446, "Capacitor, MLCC, 100pF, 50V, COG, 1%, 0402, T=0.5mm", Manufacturer=MURATA, Manufacturer_Part_Number=GCM1555C1H101FA16, Package=0402
C15 C23: library part MCD-03442, "Capacitor, MLCC, 100nF, ±10%, X7R, 25V, 0402, T=0.5mm", Manufacturer=MURATA, Manufacturer_Part_Number=GRM155R71E104KE14D, Package=0402
C16 C17: library part MCD-03442, "Capacitor, MLCC, 100nF, +/-10%, X7R, 25V, 0402, T=0.5mm", Manufacturer=MURATA, Manufacturer_Part_Number=GRM155R71E104KE14D, Package=0402
C18 C22: library part MCD-03431, "Capacitor, MLCC, 4.7uF, X5R, 10 V, 0402, ± 20%, T=0.5mm", Manufacturer=MURATA, Manufacturer_Part_Number=GRM155R61A475MEAAD, Package=0402
C19: library part MCD-03442, "Capacitor, MLCC, 100nF, ±10%, X7R, 25V, 0402, T=0.5mm", Manufacturer=MURATA, Package=0402
C20: library part MCD-00006, "Capacitor, MLCC, 100nF, 16V, X7R, +/-10%, 0402, T=0.5mm", Alternate_Manufacturer=MURATA, Alternate_Manufacturer_Part_Number=GCM155R71C104KA55D, Manufacturer=YAGEO, Manufacturer_Part_Number=CC0402KRX7R7BB104, Package=C0402
C21: library part MCD-03077, "Capacitor, MLCC, 220nF, 35V, X6S, +/-10%, 0402, T=0.5mm", Manufacturer=MURATA, Manufacturer_Part_Number=GRM155C8YA224KE01D, Package=0402
C26: library part MCD-00010, "Capacitor, MLCC, 1uF, 16V, X5R, 10%, 0603, T=0,8mm", Manufacturer=YAGEO, Manufacturer_Part_Number=CC0603KRX5R7BB105, Package=C0603
CART-1: library part MCD-00279
CN1 CN2: library part MCD-02746, "Header, 25x2, 12.7mm, VR, SMD, T=4.83mm", Manufacturer=SAMTEC
CN3: library part MCD-01531, "Header, 7x2, 1.27mm, VR, T=5.97mm, FTSH series STDC14 without Alignment Pin", Manufacturer=SAMTEC, Manufacturer_Part_Number=FTSH-107-01-L-DV-K
CN4: library part MCD-02072, "Jack_SMA, VR, PCB edge, 50R, T=7.92mm", Alternate_Manufacturer=N/A, Manufacturer=CINCH, Manufacturer_Part_Number=142-0701-851
HW1: library part MCD-03503, "RFI shield CAN, 25x20x3mm", Manufacturer=HARWIN, Manufacturer_Part_Number=S02-25200300R, Package=25x20x3mm
L1: library part MCD-01937, "Resistor, 0R, 0402, +/-5%, 1/16W", Manufacturer=YAGEO, Manufacturer_Part_Number=RC0402JR-070RL, Package=0402
L2: library part MCD-03460, "Inductor, Wire-wound, 5.6nH, ±0.1nH, 1770mA, 40mR, 0402, T=0.5mm", Manufacturer=MURATA, Package=0402
L3: library part MCD-03462, "Inductor, MLCC, 5.6nH, ±0.3nH, 650mA, 180mR, 0402, T=0.5mm", Manufacturer=MURATA, Package=0402
L4: library part MCD-03461, "Inductor, 6.8nH, +/-3%, 0.6A, 220mR, 0402, T=0.5mm", Manufacturer=MURATA
L5: library part MCD-03459, "Inductor, Wire-wound, 6.2nH, ±0.1nH, 1600mA, 56mR, 0402, T=0.5mm", Manufacturer=MURATA
L6: library part MCD-01766, "Inductor, 15nH, +/-2%, Itemp=460mA max, 0R16, 0402, T= 0.6mm, Qmin=30", Manufacturer=MURATA
L7: library part MCD-03457, "Inductor, Wire-wound, 3.6nH, ±0.1nH, 1950mA, 30mR, 0402, T=0.5mm", Manufacturer=MURATA, Package=0402
L8: library part MCD-03456, "Inductor, Wire-wound, 12nHH, ±2%, 500mA, 1405mR, 0402, T=0.5mm", Manufacturer=MURATA, Package=0402
L9: "Inductor, MLCC, 100nH, ±5%, 200mA, 1.25R, 0402, T=0.5mm", Manufacturer=MURATA, Manufacturer_Part_Number=LQG15HSR10J02, Package=0402
L10: library part MCD-03557, "Inductor, 10uH, +/-20%, 100mA, 1R36, 0805, T=0.8mm", Manufacturer=MURATA, Package=0805
R2: library part MCD-03301, "Resistor, 100K, 0402, +/-1%, 1/16W", Manufacturer=YAGEO, Manufacturer_Part_Number=RT0402FRE07100KL, Package=0402
R3 R4 R5 R6 R7 R8: library part MCD-00481, "Resistor,47R,0402,1%,1/16W", Manufacturer=YAGEO, Manufacturer_Part_Number=RC0402FR-0747RL, Package=R0402
SB1 SB2: "Resistor, 0R, 0201, Solder Bridge ON , 1/20W,", Manufacturer=YAGEO, Manufacturer_Part_Number=RC0201JR-070RL, Package=SB0201
SB3 SB4 SB5 SB6 SB7 SB8 SB9 SB10 SB11 SB12 SB13 SB14 SB15 SB16 SB17 SB18 SB19: library part MCD-01618, "Solder Bridge 0402 ON", Manufacturer=YAGEO, Manufacturer_Part_Number=RC0402JR-070RL, Package=SB0402
SC1 SC4 SC5 SC8: library part MCD-01587, "shield clip Harwin S0951-46R to fix RF shielded cavity", Manufacturer=HARWIN, Manufacturer_Part_Number=S0951-46R
SC2 SC3 SC6 SC7: library part MCD-02164, "shield clip Harwin S0981-46R to fix RF shielded cavity - SMT RFI Shield Clip, Corner (T+R)", Manufacturer=HARWIN, Manufacturer_Part_Number=S0981-46R
SC9 SC10 SC11 SC12 SC13: library part MCD-01587, "RFI shield clip mini TIN SMD", Manufacturer=HARWIN, Manufacturer_Part_Number=S0951-46R, Package=1.1x3.9mm
U1: library part MCD-03488, "IC, Programmable Sub-1GHz wireless SoC", Manufacturer=STMICROELECTRONICS, Package=QFN48
X1: library part MCD-01445, "Crystal, 32.768kHz, 7pF, +/-20ppm, 80K, 2.05x1.2mm", Manufacturer=NDK, Manufacturer_Part_Number=NX2012SA-32.768KHZ-EXS00A-MU00389, Package=2.05x1.2mm
X2: library part MCD-03559, "Crystal, 48MHz, 8pF, +/-10 ppm, 22R, 1.6x1.2mm", Manufacturer=NDK, Manufacturer_Part_Number="NX1612SA-48.000 MHz-EXS00A-CS12140", Package=1.6*1.2mm

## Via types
v1: diameter 0.45, hole 0.2, Top Layer to Bottom Layer, tented both sides, 605 vias

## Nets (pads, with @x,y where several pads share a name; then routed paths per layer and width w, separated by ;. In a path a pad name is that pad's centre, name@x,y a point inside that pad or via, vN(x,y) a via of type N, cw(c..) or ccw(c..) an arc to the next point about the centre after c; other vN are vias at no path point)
GND: C1.1 C2.1 C4.1 C7.1 C8.1 C9.1 C10.1 C11.1 C12.1 C13.1 C14.2 C15.1 C16.1 C17.1 C18.1 C19.1 C20.1 C21.1 C22.1 C23.2 C26.1 CN1.1 CN1.6 CN1.7 CN1.14 CN1.17 CN1.22 CN1.25 CN1.28 CN1.31 CN1.34 CN1.37 CN1.40 CN1.46 CN1.49 CN2.2 CN2.8 CN2.14 CN2.20 CN2.26 CN2.32 CN2.38 CN2.44 CN2.50 CN3.5 CN3.7 CN4.2 CN4.3 CN4.4 CN4.5 L3.2 R2.1 R8.1 SC1.1 SC2.1 SC3.1 SC4.1 SC5.1 SC6.1 SC7.1 SC8.1 SC9.1 SC10.1 SC11.1 SC12.1 SC13.1 U1.24 U1.39 U1.49 X2.2 X2.4 | length 233.8
  Top Layer w0.2: v1(20.828,26.95) 21.115,26.565 cw(c20.975,26.46) 21.15,26.46 U1.24@21.15,26.225
  Top Layer w0.25: v1(21.571,19.59) v1(21.9,19.919) ; U1.39@21.95,20.675 21.95,20.202 ; v1(21.9,19.919) v1@21.914,19.987 ; v1(21.9,19.919) 21.9,19.973 v1@21.914,19.987 ; v1@21.914,19.987 21.95,20.023 21.95,20.202 ; v1@21.914,19.987 21.942,20.121 ccw(c21.55,20.202) 21.95,20.202
  Top Layer w0.3: v1@16.675,23.5 v1(16.68,23.505) ; v1(24.316,28.271) 24.398,28.383 cw(c24.7,28.161) 24.435,28.426 26.974,30.965 27.168,31.159 cw(c27.327,31) 27.327,31.225 v1(27.775,31.225) v1(27.775,32.375) 28.5,33.1 v1(28.9,33.1) 30.275,33.1 30.475,32.9 v1(30.475,32.375) ; R8.1@26.975,2.525 v1(27.725,2.525) ; C13.1@29.8,28.625 v1(30.475,28.625) ; C9.1@29.8,32.375 v1(30.475,32.375) ; v1(33.475,22.895) R2.1@33.475,23.6 ; 27.7,27.9 27.775,27.975 v1(27.775,28.625) v1(27.775,29.9) 27.766,29.891 27.491,29.891 v1(26.496,28.896) v1(25.5,27.9) v1(26.5,27.9) 27.7,27.9 ; 27.7,27.9 v1(28.9,27.9) 30.214,27.9 30.475,28.161 v1(30.475,28.625) ; v1(30.475,28.625) v1(30.475,30.5) v1(30.475,32.375)
  Top Layer w0.43: v1@21.425,17.578 v1(21.425,17.9) v1@21.425,18.1
  Top Layer w0.45: v1(14.08,24.245) v1@14.085,24.25 ; v1@14.855,25.02 v1(14.85,25.025) ; C26.1@15.875,3.725 v1(15.875,4.6) ; v1(15.9,25.025) v1(14.85,25.025) ; v1(17.6,23.035) 17.053,22.488 v1(15.155,22.488) 14.58,22.488 v1(14.08,22.988) 13.425,23.642 13.425,24.642 13.809,25.025 v1(14.85,25.025)
  Top Layer w0.5: C14.2@13.625,27 v1(13.625,27.6) v1(13.625,28.1) ; v1@14.085,24.25 X2.4@14.855,24.25 ; C15.1@14.575,27 v1(14.575,27.6) v1(14.575,28.1) ; v1(15.275,29.375) v1(15.775,29.375) C11.1@16.375,29.375 ; v1(15.275,32.425) v1(15.775,32.425) C8.1@16.375,32.425 ; v1(15.275,35.475) v1(15.775,35.475) C4.1@16.375,35.475 ; X2.2@15.905,23.5 v1@16.675,23.5 ; SC1.1@16.94,36.775 v1(16.22,36.775) SC2.1@15.5,36.775 SC2.1@11.5,36.775 v1(11.5,34.125) SC2.1@11.5,32.775 SC4.1@11.5,31.243 SC4.1@11.5,30.533 SC4.1@11.5,29.433 v1(11.5,29.375) SC4.1@11.5,28.333 SC4.1@11.5,27.623 SC6.1@11.5,15.775 v1(11.5,13.091) SC6.1@11.5,11.775 SC6.1@15.5,11.775 19.69,11.775 SC8.1@19.99,11.775 SC8.1@20.7,11.775 23.31,11.775 SC7.1@27.5,11.775 v1(29.5,11.775) SC7.1@31.5,11.775 v1(31.5,14.875) SC7.1@31.5,15.775 v1(31.5,16.625) v1(31.5,17.875) 31.5,22.464 SC10.1@31.5,22.468 SC10.1@31.5,23.178 SC10.1@31.5,24.278 SC10.1@31.5,25.378 SC10.1@31.5,26.088 SC5.1@31.5,27.623 SC5.1@31.5,28.333 SC5.1@31.5,29.433 SC5.1@31.5,30.533 SC5.1@31.5,31.243 SC3.1@31.5,32.775 v1(31.5,34.125) SC3.1@31.5,36.775 SC3.1@27.5,36.775 ; SC1.1@16.94,36.775 SC1.1@17.65,36.775 SC1.1@18.75,36.775 SC1.1@19.85,36.775 SC1.1@20.56,36.775 ; v1(18,24.985) C16.1@18.176,24.985 ; v1(18.852,16.99) v1(18.852,17.49) v1(18.852,17.99) C18.1@18.852,18.39 ; v1(19.55,28.625) v1(20.05,28.625) C12.1@20.65,28.625 ; v1(19.6,31.675) v1(20.1,31.675) C10.1@20.7,31.675 ; v1(19.857,18.125) v1(19.857,18.625) v1(19.857,19.125) C19.1@19.857,19.625 ; 21.504,18.148 22.05,18.148 v1(22.05,17.848) C22.1@22.05,17.725 ; v1(23.75,17.271) C21.1@23.75,17.725 ; 24.95,36.75 v1(26.5,36.75) SC3.1@27.475,36.75 ; L3.2@25,34.425 v1(25.6,34.425) v1(26.1,34.425) ; v1(27.163,20.606) C17.1@27.163,21.131
  Top Layer w0.6: 20.23,0.758 CN3.5@20.23,3.43 20.23,5.414 ; 21.5,1.199 CN3.7@21.5,3.43 21.5,5.444
  Signal Layer 2 w0.25: v1(21.571,19.59) v1(21.9,19.919)
  Bottom Layer w0.3: 0.57,3.308 CN1.49@2.331,3.308 ; 0.57,29.978 CN1.7@2.331,29.978 ; 0.582,14.75 CN1.31@2.343,14.75 ; v1@0.582,18.56 CN1.25@2.343,18.56 ; 0.582,23.64 CN1.17@2.343,23.64 ; 0.582,33.8 CN1.1@2.343,33.8 ; 0.666,10.873 CN1.37@2.427,10.873 ; v1(4.125,21.25) 4.287,21.088 ; CN2.50@40.691,3.308 42.452,3.308 ; CN2.44@40.691,7.118 v1@42.452,7.118 ; CN2.38@40.691,10.928 42.452,10.928 ; CN2.32@40.691,14.738 42.452,14.738 ; CN2.26@40.691,18.548 v1@42.452,18.548 ; CN2.20@40.691,22.358 42.452,22.358 ; CN2.14@40.691,26.168 42.452,26.168 ; CN2.8@40.691,29.978 42.452,29.978 ; CN2.2@40.691,33.788 42.452,33.788
  Bottom Layer w0.45: CN1.49@2.343,3.32 3.501,3.17 v1(4.166,3.17) ; CN1.37@2.343,10.94 v1(4.35,10.94) ; CN1.31@2.343,14.75 v1(4.35,14.75) ; CN1.25@2.343,18.56 v1(4.35,18.56) ; CN1.17@2.343,23.64 v1(4.35,23.64) ; CN1.7@2.343,29.99 v1(4.35,29.99) ; CN1.1@2.343,33.8 v1(4.35,33.8) ; v1(4.375,6.275) 4.802,5.848 CN1.46@6.401,5.848 ; v1(4.375,14.077) 4.839,13.613 6.256,13.613 CN1.34@6.401,13.468 C7.1@8.363,13.468 ; CN1.40@6.401,9.658 8.073,9.658 ccw(c8.073,9.958) 8.178,9.677 v1(8.87,9.935) ; CN1.28@6.413,17.29 v1(8.42,17.29) ; CN1.22@6.413,21.1 v1(8.42,21.1) ; CN1.14@6.413,26.18 v1(8.42,26.18) ; CN1.6@6.413,31.26 v1(8.42,31.26) ; v1(38.637,29.531) 39.162,29.531 39.464,29.833 40.546,29.833 CN2.8@40.691,29.978 ; v1(38.672,33.776) CN2.2@40.679,33.776 ; v1(38.684,7.118) CN2.44@40.691,7.118 ; v1(38.684,10.928) CN2.38@40.691,10.928 ; v1(38.684,14.738) CN2.32@40.691,14.738 ; v1(38.684,18.548) CN2.26@40.691,18.548 ; v1(38.684,22.358) CN2.20@40.691,22.358 ; v1(38.684,26.168) CN2.14@40.691,26.168 ; v1(40,2.375) 40,3.163 40.145,3.308 CN2.50@40.691,3.308
  Bottom Layer w0.5: 4.287,21.088 CN1.22@6.401,21.088 ; v1(4.375,17) 4.653,17.278 CN1.28@6.401,17.278 ; CN1.46@6.401,5.848 8.16,5.848 v1(8.187,5.875) 8.437,6.125 v1(9.437,6.125)
  other v1: 2.052,0.459 4.852,0.459 7.652,0.459 10.452,0.459 13.252,0.459 16.052,0.459 18.851,0.459 21.651,0.459 24.451,0.459 27.251,0.459 30.051,0.459 32.851,0.459 35.65,0.459 38.45,0.459 41.25,0.459 4.836,1.39 35.562,1.375 36.625,1.5 37.938,1.5 39.312,1.5 40.625,1.5 0.45,1.591 42.55,1.591 3.375,1.625 1.4,1.924 39,2.275 30.063,2.375 41.25,2.375 3.75,2.438 4.687,2.438 29.062,2.875 8.625,3.187 30.85,3.2 31.45,3.725 30.025,4.175 0.45,4.39 42.55,4.39 19.563,5 20.875,5 22.125,5 23.437,5 25.937,5 12.05,5.2 19.563,5.813 20.875,5.813 22.125,5.813 23.437,5.813 25.937,5.813 38.475,6.325 30.4,7.125 0.45,7.19 42.55,7.19 8.187,7.75 0.45,9.99 42.55,9.99 30.8,10.575 25.219,10.907 16.3,11.775 38.675,12.2 0.45,12.79 42.55,12.79 19.563,13.15 22.4,13.185 16.571,13.372 38.675,13.45 19.964,14.754 21.5,14.754 23.055,14.8 16.3,15.2 17.5,15.2 18.775,15.216 0.45,15.59 42.55,15.59 38.625,16.063 12.525,16.375 32.875,16.6 34.087,16.625 13.125,16.918 11.5,17 13.8,17.3 21.425,17.378 38.625,17.375 32.875,17.875 34.075,17.875 15.95,17.95 13.025,18.075 0.45,18.39 42.55,18.39 21.425,18.446 38.625,19.75 33.188,20.625 38.625,21.125 0.45,21.189 42.55,21.189 13.323,21.25 14.466,21.25 21.5,21.5 23.25,21.5 25.25,21.5 13.28,22.488 22.5,22.5 24.25,22.5 10.25,22.625 23.35,23.45 21.5,23.5 25.25,23.5 8.25,23.625 38.687,23.687 10.25,23.934 0.45,23.989 42.55,23.989 22.5,24.25 24.25,24.25 9,24.875 38.687,25.063 21.5,25.25 23.25,25.25 25.25,25.25 10.25,26.4 12.187,26.688 0.45,26.789 42.55,26.789 11.5,26.875 12.812,27.125 9.5,27.25 16,27.375 19.2,27.825 15.375,27.875 12.812,28.062 18.5,28.104 11.5,28.125 33.75,28.125 8.25,28.375 10.25,28.375 16,28.375 18.75,28.729 13.563,28.875 14.625,28.875 18.5,29.375 0.45,29.589 42.55,29.589 19.5,29.625 20.65,29.652 12.525,29.977 14.525,29.977 8.25,30.125 10.25,30.125 16,30.375 18.5,30.375 22.45,30.38 22.99,30.425 24.882,30.569 11.5,30.625 20.65,30.611 31.5,30.75 19.4,30.8 10.25,31.25 22.45,31.34 16,31.375 18.5,31.375 23.188,31.428 25.11,31.43 12.525,31.477 14.525,31.477 11.5,31.875 31.5,31.875 4.375,32 32.437,32 33.563,32 34.687,32 26.275,32.05 22.45,32.299 18.5,32.375 0.45,32.389 23.188,32.388 25.11,32.389 42.55,32.389 19.425,32.55 8.25,32.625 10.25,32.625 20.65,32.615 12.525,32.977 32.437,33.062 33.563,33.062 34.687,33.062 22.45,33.259 23.188,33.348 25.11,33.349 26.625,33.348 19.25,33.375 14.542,33.414 15.75,33.5 20.65,33.575 33,33.937 34.188,33.937 22.45,34.219 23.188,34.307 27.461,34.465 29.461,34.465 15.75,34.5 12.525,34.727 14.525,34.727 1.75,34.75 4,34.75 6,34.75 8.25,34.75 10.25,34.75 33,35 35,35 37.25,35 39.25,35 41.5,35 22.45,35.178 0.45,35.189 42.55,35.189 23.188,35.267 18.25,35.5 19.375,35.5 25.11,35.493 27.461,35.527 29.461,35.527 20.65,36.138 22.45,36.138 25.073,36.198 23.188,36.227 1.75,36.25 4,36.25 6,36.25 8.25,36.25 10.25,36.25 33,36.5 35,36.5 37.25,36.5 39.25,36.5 41.5,36.5 28.875,36.75 14.085,36.775 22.766,36.836 24.56,37.495 20.65,37.613 0.45,37.988 42.55,37.988 1.75,38 4,38 6,38 8.25,38 10.25,38 12.25,38 14,38 16,38 17.75,38 19.25,38 25.5,38 27.25,38 29.25,38 31,38 33,38 35,38 37.25,38 39.25,38 41.5,38 24.093,38.124 20.65,38.573 18.073,39.125 19.224,39.125 24.05,39.25 25.15,39.25 20.65,39.533 22.45,39.533 1.75,40.25 4,40.25 6,40.25 8.25,40.25 10.25,40.25 12.25,40.25 14,40.25 16,40.25 17.75,40.25 19.25,40.25 24,40.25 25.5,40.25 27.25,40.25 29.25,40.25 31,40.25 33,40.25 35,40.25 37.25,40.25 39.25,40.25 41.5,40.25 20.65,40.492 22.45,40.492 0.45,40.788 42.55,40.788 19.625,41.125 20.65,41.452 15.375,41.5 16.625,41.5 17.75,41.5 18.75,41.5 24.25,41.5 25.25,41.5 26.375,41.5 27.625,41.5 15.375,42.25 18.75,42.25 24.25,42.25 27.625,42.25 20.65,42.411 22.45,42.411 1.75,42.5 4,42.5 6,42.5 8.25,42.5 10.25,42.5 12.25,42.5 14,42.5 29.25,42.5 31,42.5 33,42.5 35,42.5 37.25,42.5 39.25,42.5 41.5,42.5 15.375,43.25 18.75,43.25 24.25,43.25 27.625,43.25 20.65,43.371 22.45,43.371 0.45,43.588 42.55,43.588 11,43.75 13,43.75 29.25,44 31,44 33,44 35,44 37.25,44 41.5,44 15.375,44.25 18.75,44.25 24.25,44.25 27.625,44.25 20.65,44.331 22.45,44.331 1.75,45.25 4,45.25 10.25,45.25 11.75,45.25 13.5,45.25 15.375,45.25 18.75,45.25 24.25,45.25 27.625,45.25 20.65,45.29 22.45,45.29 29.25,45.5 31,45.5 33,45.5 35,45.5 37.25,45.5 39.25,45.5 41.5,45.5 18.75,46.25 20.65,46.25 22.45,46.25 24.25,46.25 0.682,46.3 3.482,46.3 6.282,46.3 9.081,46.3 11.881,46.3 15.325,46.3 27.675,46.3 28.68,46.3 31.48,46.3 34.28,46.3 37.08,46.3 39.88,46.3 42.34,46.3
GPIO3/BOOT0: CN1.9 R2.2 U1.10 | length 81.9
  Top Layer w0.15: v1(4.375,10.035) 4.675,10.335 9.655,10.335 10.07,9.92 v1(10.07,8.22) ; U1.10@26.125,24.85 28.861,24.85 v1(29.186,25.175) 29.186,25.124 29.237,25.124 29.76,24.601 29.76,20.641 29.525,20.406 29.525,18.759 29.575,18.709 29.575,17.951 29.825,17.701 29.825,15.125 30.06,14.89 30.06,13.673 29.537,13.15 v1(28.975,13.15) ; R2.2@33.475,24.5 v1(33.475,25.175)
  Signal Layer 2 w0.15: v1(4.35,28.72) 5.935,27.135 5.935,24.235 2.935,21.235 2.935,10.156 3.056,10.035 v1(4.375,10.035) ; v1(10.07,8.22) 10.597,8.22 cw(c10.597,8.07) 10.704,8.176 14.742,4.137 20.088,4.137 20.575,3.651 26.3,3.651 26.69,4.041 26.69,4.725 28.975,7.01 28.975,7.958 28.975,10.907 v1(28.975,13.15) ; v1(29.186,25.175) v1(33.475,25.175)
  Bottom Layer w0.45: CN1.9@2.343,28.72 v1(4.35,28.72)
GPIO5/SWDIO: CN1.13 R3.2 U1.1 | length 69.7
  Top Layer w0.15: v1(4.305,9.175) 4.591,9.461 v1(9.5,9.461) ; U1.1@26.125,21.25 26.125,20.099 26.363,19.861 26.363,19.363 27.775,17.951 v1(27.775,12.699)
  Top Layer w0.3: v1(18.125,9.326) 18.125,10.225 18.3,10.4 R3.2@18.95,10.4
  Signal Layer 2 w0.15: v1(4.305,9.175) 2.969,9.175 2.5,9.644 2.5,23.925 2.825,24.25 4.37,24.25 4.836,24.716 4.836,25.694 v1(4.35,26.18) ; v1(9.5,9.461) 10.267,9.461 10.978,8.75 13.451,6.276 13.783,5.945 16.798,5.945 v1(16.855,5.888) 17.292,6.325 27.04,6.325 28.375,7.66 28.375,12.099 v1(27.775,12.699)
  Bottom Layer w0.15: v1(16.855,5.888) 17.525,5.888 18.125,6.487 v1(18.125,9.326)
  Bottom Layer w0.45: CN1.13@2.343,26.18 v1(4.35,26.18)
